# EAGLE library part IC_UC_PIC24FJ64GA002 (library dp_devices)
16-bit General Purpose Flash Microcontroller
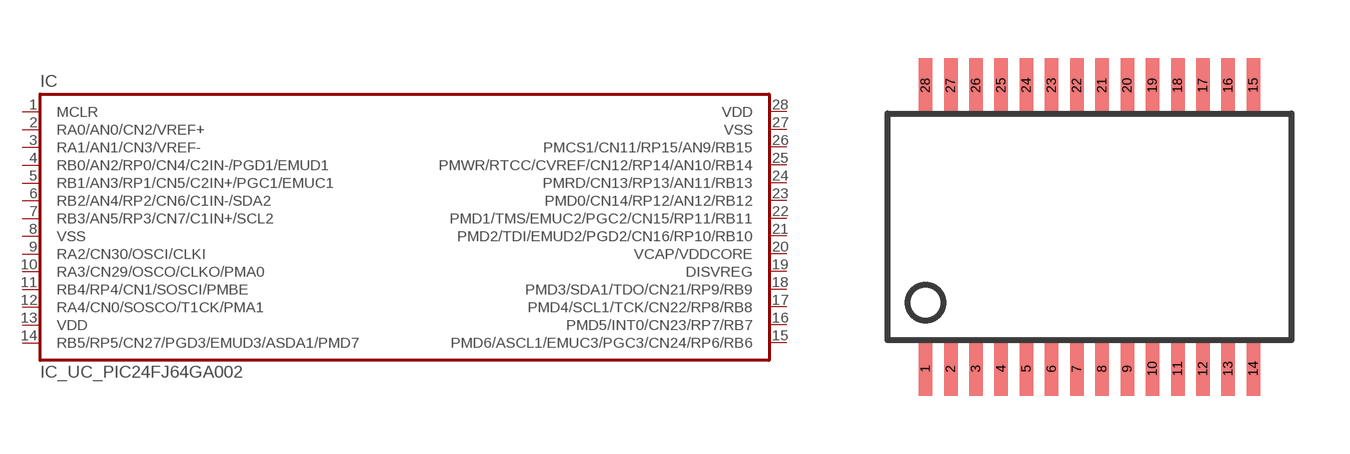
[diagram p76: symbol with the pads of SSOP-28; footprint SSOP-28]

Designator prefix IC

## IC_UC_PIC24FJ64GA002  [SSOP-28]
1  MCLR  in
2  RA0/AN0/CN2/VREF+
3  RA1/AN1/CN3/VREF-
4  RB0/AN2/RP0/CN4/C2IN-/PGD1/EMUD1
5  RB1/AN3/RP1/CN5/C2IN+/PGC1/EMUC1
6  RB2/AN4/RP2/CN6/C1IN-/SDA2
7  RB3/AN5/RP3/CN7/C1IN+/SCL2
8  VSS  sup
9  RA2/CN30/OSCI/CLKI
10  RA3/CN29/OSCO/CLKO/PMA0
11  RB4/RP4/CN1/SOSCI/PMBE
12  RA4/CN0/SOSCO/T1CK/PMA1
13  VDD  sup
14  RB5/RP5/CN27/PGD3/EMUD3/ASDA1/PMD7
15  PMD6/ASCL1/EMUC3/PGC3/CN24/RP6/RB6
16  PMD5/INT0/CN23/RP7/RB7
17  PMD4/SCL1/TCK/CN22/RP8/RB8
18  PMD3/SDA1/TDO/CN21/RP9/RB9
19  DISVREG  pwr
20  VCAP/VDDCORE  pwr
21  PMD2/TDI/EMUD2/PGD2/CN16/RP10/RB10
22  PMD1/TMS/EMUC2/PGC2/CN15/RP11/RB11
23  PMD0/CN14/RP12/AN12/RB12
24  PMRD/CN13/RP13/AN11/RB13
25  PMWR/RTCC/CVREF/CN12/RP14/AN10/RB14
26  PMCS1/CN11/RP15/AN9/RB15
27  VSS  sup
28  VDD  sup

## Footprint SSOP-28 (pad centres in mm)
SSOP28
smd 0.348 x 1.397: 1 -4.225,-3.656; 2 -3.575,-3.656; 3 -2.925,-3.656; 4 -2.275,-3.656; 5 -1.625,-3.656; 6 -0.975,-3.656; 7 -0.325,-3.656; 8 0.325,-3.656; 9 0.975,-3.656; 10 1.625,-3.656; 11 2.275,-3.656; 12 2.925,-3.656; 13 3.575,-3.656; 14 4.225,-3.656; 15 4.225,3.656; 16 3.575,3.656; 17 2.925,3.656; 18 2.275,3.656; 19 1.625,3.656; 20 0.975,3.656; 21 0.325,3.656; 22 -0.325,3.656; 23 -0.975,3.656; 24 -1.625,3.656; 25 -2.275,3.656; 26 -2.925,3.656; 27 -3.575,3.656; 28 -4.225,3.656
